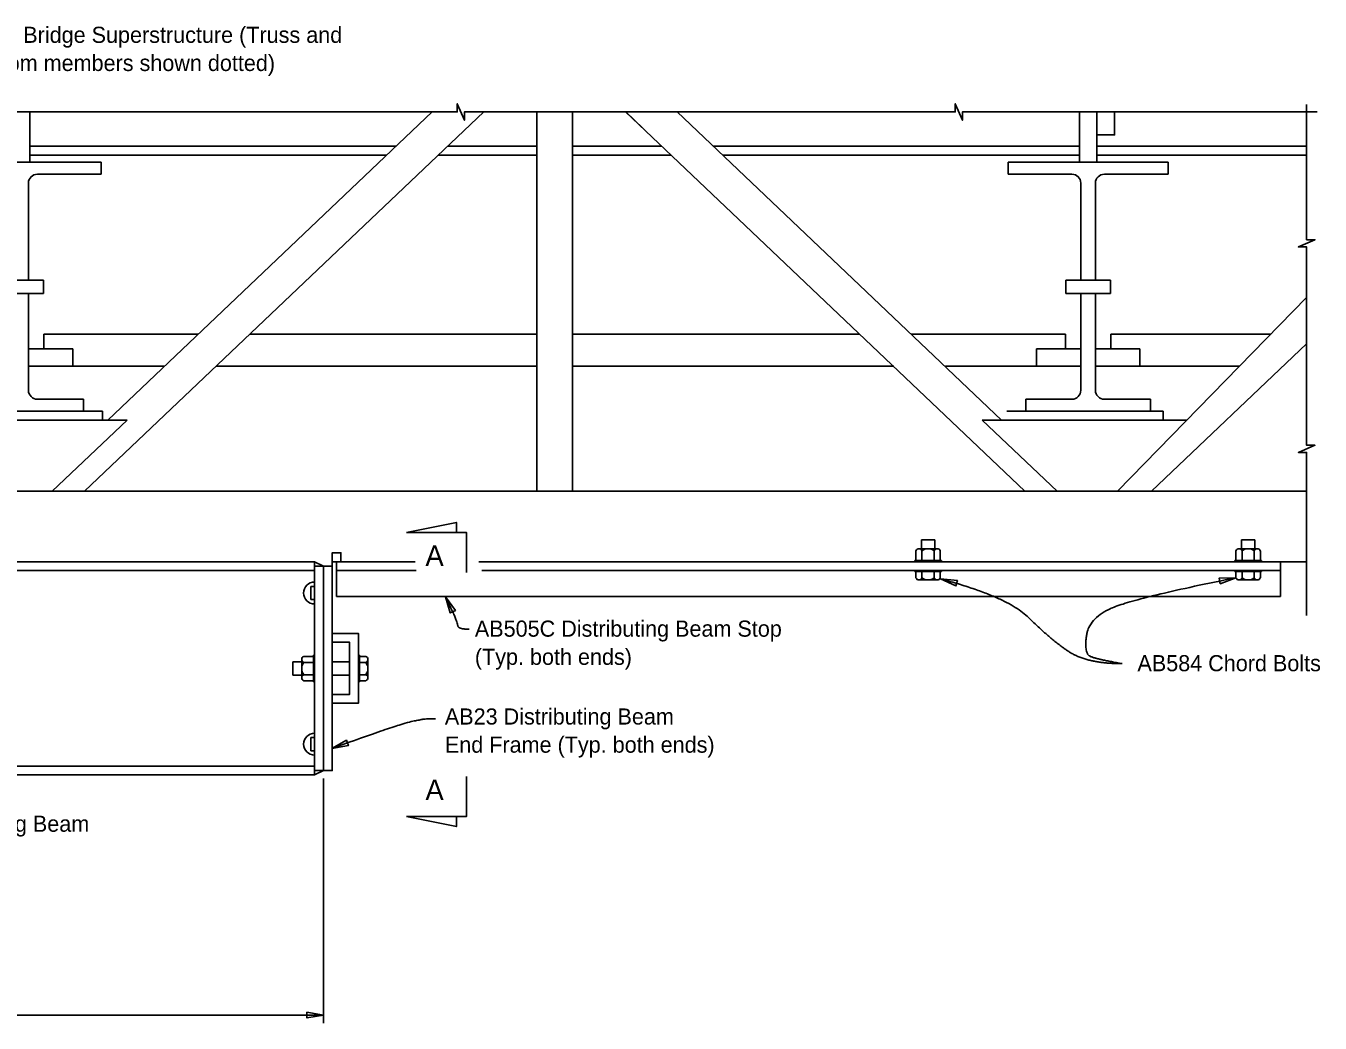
# Model space of a CAD drawing. Extents: x 0.1 to 14.7, y 0.1 to 9.6.
# Drawn here: x 8.63 to 14.7, y 4.71 to 9.39 of the extents above; entities that cross this region are included whole.
import ezdxf

# ---------------------------------------------------------------- set-up
doc = ezdxf.new("R2010")
doc.units = 0
for name, color, linetype in [('Dimension', 7, 'Continuous'), ('SteelMisc', 7, 'Continuous'), ('SteelMisc_h', 7, 'Continuous'), ('Symbols', 7, 'Continuous'), ('TextStructures', 7, 'Continuous')]:
    doc.layers.add(name, color=color, linetype=linetype)

msp = doc.modelspace()

# ---------------------------------------------------------------- linework, layer by layer
at = {"layer": 'Dimension'}
for p, q in [((10.029, 5.8602), (10.029, 4.7139)), ((1.6956, 4.7517), (10.029, 4.7517))]:
    msp.add_line(p, q, dxfattribs=at)
for points in [[(12.9209, 6.7963), (12.9929, 6.7634), (12.9998, 6.789)], [(14.3052, 6.802), (14.226, 6.7995), (14.2313, 6.7736)], [(10.6004, 6.713), (10.6233, 6.6371), (10.647, 6.6489)], [(10.0676, 6.001), (10.1455, 6.0152), (10.1365, 6.0401)], [(9.9509, 4.765), (10.029, 4.7517), (9.9509, 4.7385)]]:
    msp.add_lwpolyline(points, close=True, dxfattribs=at)
for points in [[(13.7726, 6.3991), (13.6045, 6.3991), (13.4308, 6.5175), (13.236, 6.7123), (12.9209, 6.7963)], [(13.7726, 6.3991), (13.6504, 6.4201), (13.5931, 6.4468), (13.616, 6.613), (13.8318, 6.7066), (14.3052, 6.802)], [(10.7113, 6.5605), (10.6578, 6.5605), (10.6578, 6.5971), (10.6004, 6.713)], [(10.5545, 6.1401), (10.5293, 6.1401), (10.4976, 6.1401), (10.3754, 6.1127), (10.0676, 6.001)]]:
    msp.add_open_spline(points, degree=2, dxfattribs=at)
at = {"layer": 'SteelMisc'}
for p, q in [((8.6527, 8.7495), (8.6527, 8.9852)), ((10.7798, 8.9852), (8.9089, 7.2078)), ((10.5378, 8.9852), (9.0176, 7.5411)), ((11.029, 7.2078), (11.029, 8.9852)), ((11.1956, 7.2078), (11.1956, 8.9852)), ((11.4448, 8.9852), (13.3157, 7.2078)), ((11.4454, 8.9852), (11.5273, 8.9075)), ((11.6868, 8.9852), (13.207, 7.5411)), ((13.5718, 8.7495), (13.5718, 8.9852)), ((13.6527, 8.7495), (13.6527, 8.9852)), ((8.6527, 8.8247), (10.3688, 8.8247)), ((10.6108, 8.8247), (11.029, 8.8247)), ((11.5273, 8.8247), (11.1956, 8.8247)), ((11.6138, 8.8247), (11.1956, 8.8247)), ((13.5718, 8.8247), (11.8558, 8.8247)), ((13.6529, 8.8247), (14.6363, 8.8247)), ((8.2372, 8.7495), (8.9871, 8.7495)), ((8.6527, 8.783), (10.3249, 8.783)), ((8.9871, 8.7495), (8.9871, 8.6936)), ((10.5669, 8.783), (11.029, 8.783)), ((11.5273, 8.783), (11.1956, 8.783)), ((11.6576, 8.783), (11.1956, 8.783)), ((13.5718, 8.783), (11.8997, 8.783)), ((13.2374, 8.6936), (13.2374, 8.7495)), ((13.2374, 8.7495), (13.9873, 8.7495)), ((13.6529, 8.783), (14.6363, 8.783)), ((13.9873, 8.7495), (13.9873, 8.6936)), ((8.9871, 8.6936), (8.6881, 8.6936)), ((13.5365, 8.6936), (13.2374, 8.6936)), ((13.9873, 8.6936), (13.6883, 8.6936)), ((8.6464, 8.6519), (8.6464, 8.1974)), ((13.5782, 8.1974), (13.5782, 8.6519)), ((13.6466, 8.6519), (13.6466, 8.1974)), ((8.5081, 8.1974), (8.7164, 8.1974)), ((8.7164, 8.1974), (8.7164, 8.1349)), ((13.5083, 8.1974), (13.5083, 8.1349)), ((13.5083, 8.1974), (13.7166, 8.1974)), ((13.7166, 8.1974), (13.7166, 8.1349)), ((8.5081, 8.1349), (8.7164, 8.1349)), ((8.6464, 8.1349), (8.6464, 7.6804)), ((13.5083, 8.1349), (13.7166, 8.1349)), ((13.5782, 7.6804), (13.5782, 8.1349)), ((13.6466, 8.1349), (13.6466, 7.6804)), ((13.7502, 7.2078), (14.6363, 8.1155)), ((8.7185, 7.9436), (8.7185, 7.8745)), ((13.5061, 7.9436), (13.5061, 7.8745)), ((13.7187, 7.9436), (13.7187, 7.8745)), ((14.6363, 7.8987), (13.9091, 7.2078)), ((8.6464, 7.8745), (8.8547, 7.8745)), ((8.8547, 7.8745), (8.8547, 7.7936)), ((13.3699, 7.8745), (13.3699, 7.7936)), ((13.5782, 7.8745), (13.3699, 7.8745)), ((13.6466, 7.8745), (13.8549, 7.8745)), ((13.8549, 7.8745), (13.8549, 7.7936)), ((8.2606, 7.5828), (8.9931, 7.5828)), ((8.6881, 7.6387), (8.9038, 7.6387)), ((8.9038, 7.6387), (8.9038, 7.5828)), ((8.9931, 7.5828), (8.9931, 7.54)), ((13.964, 7.5828), (13.2314, 7.5828)), ((13.3207, 7.5828), (13.3207, 7.6387)), ((13.3207, 7.6387), (13.5365, 7.6387)), ((13.6883, 7.6387), (13.904, 7.6387)), ((13.904, 7.6387), (13.904, 7.5828)), ((13.964, 7.5828), (13.964, 7.5422)), ((8.149, 7.5411), (9.1084, 7.5411)), ((9.1084, 7.5411), (8.7576, 7.2078)), ((14.0756, 7.5411), (13.1162, 7.5411)), ((13.1162, 7.5411), (13.467, 7.2078)), ((0.1675, 7.2078), (14.6363, 7.2078)), ((12.8311, 6.9379), (12.8311, 6.9802)), ((12.8935, 6.9802), (12.8311, 6.9802)), ((12.8935, 6.9379), (12.8935, 6.9802)), ((14.3311, 6.9379), (14.3311, 6.9802)), ((14.3935, 6.9802), (14.3311, 6.9802)), ((14.3935, 6.9379), (14.3935, 6.9802)), ((12.8052, 6.9274), (12.8052, 6.8831)), ((12.9043, 6.9379), (12.8203, 6.9379)), ((12.8337, 6.9274), (12.8337, 6.8831)), ((12.8908, 6.8831), (12.8908, 6.9274)), ((12.9194, 6.9274), (12.9194, 6.8831)), ((14.3052, 6.9274), (14.3052, 6.8831)), ((14.4043, 6.9379), (14.3203, 6.9379)), ((14.3337, 6.9274), (14.3337, 6.8831)), ((14.3908, 6.8831), (14.3908, 6.9274)), ((14.4194, 6.9274), (14.4194, 6.8831)), ((1.7373, 6.8771), (9.9873, 6.8771)), ((9.9873, 5.8771), (9.9873, 6.8771)), ((10.029, 6.8563), (9.9873, 6.8771)), ((10.029, 6.8563), (9.9873, 6.8563)), ((10.4593, 6.8771), (10.0699, 6.8771)), ((10.0903, 6.8771), (10.0903, 6.7131)), ((14.5135, 6.8771), (10.7573, 6.8771)), ((12.7998, 6.8831), (12.7998, 6.8774)), ((12.9248, 6.8831), (12.7998, 6.8831)), ((12.9248, 6.8831), (12.9248, 6.8774)), ((14.2998, 6.8831), (14.2998, 6.8774)), ((14.4248, 6.8831), (14.2998, 6.8831)), ((14.4248, 6.8831), (14.4248, 6.8774)), ((14.5135, 6.8771), (14.6363, 6.8771)), ((14.5135, 6.7131), (14.5135, 6.8771)), ((4.7489, 6.8362), (9.9873, 6.8362)), ((9.9693, 6.6995), (9.9693, 6.7608)), ((9.9693, 6.7608), (9.9873, 6.7608)), ((9.9873, 6.6995), (9.9693, 6.6995)), ((14.5135, 6.7131), (10.0903, 6.7131)), ((9.9373, 6.4331), (9.9816, 6.4331)), ((9.9816, 6.4385), (9.9873, 6.4385)), ((9.9816, 6.4385), (9.9816, 6.3135)), ((10.198, 6.4385), (10.1924, 6.4385)), ((10.198, 6.4385), (10.198, 6.3135)), ((10.2266, 6.4331), (10.198, 6.4331)), ((9.9268, 6.4072), (9.8845, 6.4072)), ((9.8845, 6.4072), (9.8845, 6.3448)), ((9.9268, 6.418), (9.9268, 6.3339)), ((9.9816, 6.4045), (9.9373, 6.4045)), ((10.1515, 6.4072), (10.0699, 6.4072)), ((10.198, 6.4045), (10.2266, 6.4045)), ((10.2371, 6.418), (10.2371, 6.3339)), ((9.9268, 6.3448), (9.8845, 6.3448)), ((9.9373, 6.3474), (9.9816, 6.3474)), ((9.9373, 6.3189), (9.9816, 6.3189)), ((9.9816, 6.3135), (9.9873, 6.3135)), ((10.1515, 6.3448), (10.0699, 6.3448)), ((10.198, 6.3135), (10.1924, 6.3135)), ((10.2266, 6.3474), (10.198, 6.3474)), ((10.2266, 6.3189), (10.198, 6.3189)), ((9.9693, 6.0524), (9.9693, 5.9911)), ((9.9873, 6.0524), (9.9693, 6.0524)), ((9.9693, 5.9911), (9.9873, 5.9911)), ((4.862, 5.9181), (9.9873, 5.9181)), ((10.029, 5.898), (9.9873, 5.898)), ((10.029, 5.898), (9.9873, 5.8771)), ((4.8662, 5.8771), (9.9873, 5.8771))]:
    msp.add_line(p, q, dxfattribs=at)
for points in [[(13.7361, 8.9852), (13.7361, 8.8774), (13.6527, 8.8774), (13.6527, 8.9852)], [(9.4413, 7.9436), (8.7185, 7.9436)], [(11.029, 7.9436), (9.6833, 7.9436)], [(11.1956, 7.9436), (11.5273, 7.9436)], [(11.1956, 7.9436), (12.5409, 7.9436)], [(12.7853, 7.9436), (13.5061, 7.9436)], [(14.4685, 7.9436), (13.7187, 7.9436)], [(8.6464, 7.7936), (9.2834, 7.7936)], [(9.5254, 7.7936), (11.029, 7.7936)], [(11.5273, 7.7936), (11.1956, 7.7936)], [(12.7021, 7.7936), (11.1956, 7.7936)], [(13.5782, 7.7936), (12.9444, 7.7936)], [(13.6466, 7.7936), (14.322, 7.7936)], [(8.9038, 7.5828), (8.6123, 7.5828), (8.3205, 7.5828)], [(13.904, 7.5828), (13.6125, 7.5828), (13.3207, 7.5828)], [(10.1107, 6.8775), (10.1107, 6.9188), (10.0699, 6.9188), (10.0699, 6.8362)]]:
    msp.add_lwpolyline(points, dxfattribs=at)
for points in [[(10.029, 5.898), (10.0699, 5.898), (10.0699, 6.8564), (10.029, 6.8564)], [(10.0699, 6.5406), (10.1924, 6.5406), (10.1924, 6.2138), (10.0699, 6.2138), (10.0699, 6.2547), (10.1515, 6.2547), (10.1515, 6.4997), (10.0699, 6.4997)]]:
    msp.add_lwpolyline(points, close=True, dxfattribs=at)
for centre, radius, start, end in [((8.6881, 8.6519), 0.0417, 90, 180), ((13.5365, 8.6519), 0.0417, 0, 90), ((13.6883, 8.6519), 0.0417, 90, 180), ((8.6881, 7.6804), 0.0417, 180, 270), ((13.5365, 7.6804), 0.0417, 270, 360), ((13.6883, 7.6804), 0.0417, 180, 270), ((12.8195, 6.923), 0.0149, 86.98464, 162.74424), ((12.8195, 6.923), 0.0149, 17.25576, 86.98464), ((12.8623, 6.8939), 0.0441, 49.64006, 130.35994), ((12.9051, 6.923), 0.0149, 93.01536, 162.74424), ((12.9051, 6.923), 0.0149, 17.25576, 93.01536), ((14.3195, 6.923), 0.0149, 86.98464, 162.74424), ((14.3195, 6.923), 0.0149, 17.25576, 86.98464), ((14.3623, 6.8939), 0.0441, 49.64006, 130.35994), ((14.4051, 6.923), 0.0149, 93.01536, 162.74424), ((14.4051, 6.923), 0.0149, 17.25576, 93.01536), ((9.9873, 6.7302), 0.0514, 90.02786, 269.97214), ((9.9417, 6.4188), 0.0149, 107.25576, 183.01536), ((10.2222, 6.4188), 0.0149, 356.98464, 72.74424), ((9.9417, 6.4188), 0.0149, 183.01536, 252.74424), ((9.9709, 6.376), 0.0441, 139.64006, 220.35994), ((10.2222, 6.4188), 0.0149, 287.25576, 356.98464), ((10.193, 6.376), 0.0441, 319.64006, 40.35994), ((9.9417, 6.3331), 0.0149, 107.25576, 176.98464), ((9.9417, 6.3331), 0.0149, 176.98464, 252.74424), ((10.2222, 6.3331), 0.0149, 3.01536, 72.74424), ((10.2222, 6.3331), 0.0149, 287.25576, 3.01536), ((9.9873, 6.0218), 0.0514, 90.02786, 269.97214)]:
    msp.add_arc(centre, radius, start, end, dxfattribs=at)
at = {"layer": 'SteelMisc_h'}
for p, q in [((10.4628, 6.8362), (10.0903, 6.8362)), ((14.5135, 6.8362), (10.7717, 6.8362)), ((12.7998, 6.8306), (12.7998, 6.8362)), ((12.9248, 6.8306), (12.7998, 6.8306)), ((12.8052, 6.802), (12.8052, 6.8306)), ((12.8337, 6.802), (12.8337, 6.8306)), ((12.8908, 6.8306), (12.8908, 6.802)), ((12.9194, 6.802), (12.9194, 6.8306)), ((12.9248, 6.8306), (12.9248, 6.8362)), ((14.2998, 6.8306), (14.2998, 6.8362)), ((14.4248, 6.8306), (14.2998, 6.8306)), ((14.3052, 6.802), (14.3052, 6.8306)), ((14.3337, 6.802), (14.3337, 6.8306)), ((14.3908, 6.8306), (14.3908, 6.802)), ((14.4194, 6.802), (14.4194, 6.8306)), ((14.4248, 6.8306), (14.4248, 6.8362)), ((12.9043, 6.7915), (12.8203, 6.7915)), ((14.4043, 6.7915), (14.3203, 6.7915))]:
    msp.add_line(p, q, dxfattribs=at)
for centre, radius, start, end in [((12.8195, 6.8064), 0.0149, 197.25576, 273.01536), ((12.8195, 6.8064), 0.0149, 273.01536, 342.74424), ((12.8623, 6.8356), 0.0441, 229.64006, 310.35994), ((12.9051, 6.8064), 0.0149, 197.25576, 266.98464), ((12.9051, 6.8064), 0.0149, 266.98464, 342.74424), ((14.3195, 6.8064), 0.0149, 197.25576, 273.01536), ((14.3195, 6.8064), 0.0149, 273.01536, 342.74424), ((14.3623, 6.8356), 0.0441, 229.64006, 310.35994), ((14.4051, 6.8064), 0.0149, 197.25576, 266.98464), ((14.4051, 6.8064), 0.0149, 266.98464, 342.74424)]:
    msp.add_arc(centre, radius, start, end, dxfattribs=at)
at = {"layer": 'Symbols'}
for points in [[(6.1123, 8.9852), (7.7693, 8.9852), (7.7693, 9.024), (7.803, 8.9465), (7.803, 8.9852), (9.0387, 8.9852)], [(9.0387, 8.9852), (10.6558, 8.9852), (10.6558, 9.024), (10.6896, 8.9465), (10.6896, 8.9852), (11.6248, 8.9852)], [(11.029, 8.9852), (12.9896, 8.9852), (12.9896, 9.024), (13.0234, 8.9465), (13.0234, 8.9852), (14.6854, 8.9852)], [(14.6363, 7.7688), (14.6363, 8.3524), (14.5976, 8.3524), (14.6751, 8.3861), (14.6363, 8.3861), (14.6363, 9.0201)], [(14.6363, 6.6249), (14.6363, 7.3892), (14.5976, 7.3892), (14.6751, 7.4229), (14.6363, 7.4229), (14.6363, 7.7688)], [(10.6518, 7.0141), (10.6987, 7.0141), (10.6987, 6.8266)], [(10.6518, 5.682), (10.6987, 5.682), (10.6987, 5.8695)]]:
    msp.add_lwpolyline(points, dxfattribs=at)
for points in [[(10.4174, 7.0141), (10.6518, 7.0141), (10.6518, 7.061)], [(10.4174, 5.682), (10.6518, 5.682), (10.6518, 5.6351)]]:
    msp.add_lwpolyline(points, close=True, dxfattribs=at)

# ---------------------------------------------------------------- texts
at = {"layer": 'TextStructures'}
for s, height, p in [('Detour Bridge Superstructure (Truss and ', 0.0756, (8.2905, 9.3092)), ('Transom members shown dotted)', 0.0756, (8.2905, 9.1772)), ('A', 0.096, (10.5067, 6.8572)), ('AB505C Distributing Beam Stop', 0.0756, (10.7383, 6.5254)), ('(Typ. both ends)', 0.0756, (10.7383, 6.3934)), ('AB584 Chord Bolts', 0.0756, (13.8434, 6.3635)), ('AB23 Distributing Beam ', 0.0756, (10.5977, 6.1136)), ('End Frame (Typ. both ends)', 0.0756, (10.5977, 5.9816)), ('A', 0.096, (10.5067, 5.7595)), ('AB22 Distributing Beam', 0.0756, (7.8579, 5.6109))]:
    msp.add_text(s, height=height, dxfattribs=at).set_placement(p)

doc.saveas('drawing.dxf')
